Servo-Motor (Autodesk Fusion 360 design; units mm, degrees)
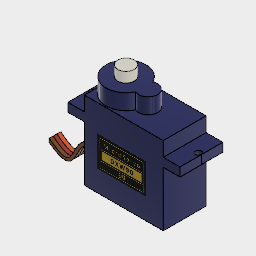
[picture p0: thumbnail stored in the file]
sketch "Sketch1" plane through (0, 0, 0) normal (0, -1, 0) x axis (1, 0, 0)
  line L1 (-11.275, 4.55) -> (-16.065, 4.55)
  line L2 (-11.275, -11.2) -> (-11.275, 4.55)
  line L3 (11.275, -11.2) -> (-11.275, -11.2)
  line L4 (11.275, 4.55) -> (11.275, -11.2)
  line L5 (16.065, 4.55) -> (11.275, 4.55)
  line L6 (16.065, 7.05) -> (16.065, 4.55)
  line L7 (11.275, 7.05) -> (16.065, 7.05)
  line L8 (11.275, 11.2) -> (11.275, 7.05)
  line L9 (-11.275, 11.2) -> (11.275, 11.2)
  line L10 (-11.275, 7.05) -> (-11.275, 11.2)
  line L11 (-16.065, 7.05) -> (-11.275, 7.05)
  line L12 (-16.065, 4.55) -> (-16.065, 7.05)
  line L13 (11.275, 11.2) -> (-11.275, 11.2)
  line L14 (11.275, 7.05) -> (11.275, 11.2)
  line L15 (16.065, 7.05) -> (11.275, 7.05)
  line L16 (16.065, 7.05) -> (16.065, 4.55)
  line L17 (11.275, 4.55) -> (16.065, 4.55)
  line L18 (11.275, -11.2) -> (11.275, 4.55)
  line L19 (-11.275, -11.2) -> (11.275, -11.2)
  line L20 (-11.275, 4.55) -> (-11.275, -11.2)
  line L21 (-16.065, 7.05) -> (-16.065, 4.55)
  line L22 (-11.275, 7.05) -> (-16.065, 7.05)
  line L23 (-11.275, 11.2) -> (-11.275, 7.05)
  line L24 (-16.065, 4.55) -> (-11.275, 4.55)
extrude "Extrude1" sketch "Sketch1" blind 12.3
move "Move1"
sketch "Sketch2" plane through (0, 0, 11.2) normal (0, 0, 1) x axis (-1, 0, 0)
  line L1 (11.275, -6.15) -> (-11.275, -6.15)
  line L2 (11.275, 6.15) -> (11.275, -6.15)
  line L3 (-11.275, 6.15) -> (11.275, 6.15)
  line L4 (-11.275, -6.15) -> (-11.275, 6.15)
  line L5 (16.065, 6.15) -> (16.065, -6.15)
  line L6 (-16.065, 6.15) -> (-16.065, -6.15)
  line L7 (-16.065, 0) -> (16.065, 0)
  line L8 (0, -6) -> (0, 6.15)
  line L9 (-3.525, 0) -> (-11.275, 0)
  line L10 (-3.525, -3) -> (-3.525, 3.3214)
  circle C1 centre (15.19, 0) radius 0.875
  circle C2 centre (-15.19, 0) radius 0.875
  arc A1 centre (-0.81, 0) radius 2.715 clockwise from (0.3298, -2.4642) to (0.3298, 2.4642)
  arc A2 centre (5.525, 0) radius 5.75 clockwise from (0.3298, 2.4642) to (0.3298, -2.4642)
  point P17 (-11.275, 0)
  point P18 (-3.525, 0)
  dimension "d10" diameter C1 = 1.75
  dimension "d11" diameter A2 = 11.5
  dimension "d12" distance P17 P18 = 7.75
  dimension "d13" diameter A1 = 5.43
extrude "Extrude2" sketch "Sketch2" profile of A2 A1 blind 4.45
component_from_bodies "Body->Comp"
sketch "Sketch1" plane through (0, 0, 15.65) normal (0, 0, 1) x axis (-1, 0, 0)
  arc A1 centre (5.525, 0) radius 5.75 clockwise from (0.3298, 2.4642) to (0.3298, -2.4642)
  arc A2 centre (-0.81, 0) radius 2.715 clockwise from (0.3298, -2.4642) to (0.3298, 2.4642)
  circle C1 centre (5.525, 0) radius 2.35
  dimension "d16" diameter C1 = 4.7
extrude "Extrude1" sketch "Sketch1" profile of C1 blind 2.88
joint "Assemble1" alignAngle 0 alignOffsetX 0 alignOffsetY 0 alignOffsetZ 0
decal "Decal1"
decal "Decal2"
extrude "Extrude1" sketch "Sketch2" profile of C1 C2 blind -2.5
sketch "Sketch1" plane through (-11.275, 0, 0) normal (-1, 0, 0) x axis (0, -1, 0)
  line L1 (-6.15, -11.2) -> (-6.15, 4.55)
  line L2 (6.15, -11.2) -> (-6.15, -11.2)
  line L3 (6.15, 4.55) -> (6.15, -11.2)
  line L4 (-6.15, 4.55) -> (6.15, 4.55)
  line L5 (0, -6.45) -> (0, -11.2)
  line L6 (1.65, -5.45) -> (1.65, -6.45)
  line L7 (-1.65, -5.45) -> (1.65, -5.45)
  line L8 (-1.65, -6.45) -> (-1.65, -5.45)
  line L9 (1.65, -6.45) -> (-1.65, -6.45)
  line L10 (-0.55, -5.45) -> (-1.65, -5.45)
  line L11 (0.55, -5.45) -> (-0.55, -5.45)
  line L12 (0.55, -6.45) -> (0.55, -5.45)
  line L13 (-0.55, -6.45) -> (-0.55, -5.45)
  point P7 (0, -6.45)
  point P8 (-1.65, -6.45)
  point P11 (-1.65, -5.45)
  point P9 (1.65, -6.45)
  point P12 (-0.55, -5.45)
  point P13 (0.55, -5.45)
  dimension "d35" distance P7 P8 = 1.65 (= "( 3.3 / 2 ) * 1 mm")
  dimension "d36" distance P8 P11 = 1
  dimension "d37" distance P8 P9 = 3.3
  dimension "d38" distance P11 P12 = 1.1 (= "( 3.3 / 3 ) * 1 mm")
  dimension "d39" distance P12 P13 = 1.1 (= "( 3.3 / 3 ) * 1 mm")
sketch "Sketch2" plane through (0, 0, 0) normal (0, 1, 0) x axis (1, 0, 0)
  curve K1 (-26, 10) -> (-11.275, 6.45)
sweep "Sweep1" sketch "Sketch1" bodies "Orange"
sweep "Sweep2" sketch "Sketch1" bodies "Red"
sweep "Sweep3" sketch "Sketch1" bodies "Brown"
position "Position1"
ground "Ground1"
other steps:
base_feature "Base Feature"
create_component "CreateComponent1"
remove_body "RemoveBody1"
create_component "CreateComponent2"
joint_origin "JointOrigin1" OffsetX 0 OffsetY 0 OffsetZ 0 AngleZ 0
joint_origin "JointOrigin1" OffsetX 0 OffsetY 0 OffsetZ 0 AngleZ 0
create_component "CreateComponent3"
named bodies: "Orange", "Red", "Brown"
